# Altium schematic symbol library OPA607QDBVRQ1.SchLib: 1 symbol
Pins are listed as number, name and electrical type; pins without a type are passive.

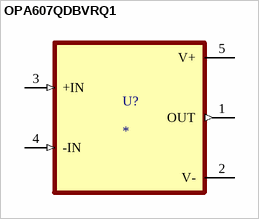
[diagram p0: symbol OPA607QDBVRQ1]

## OPA607QDBVRQ1
designator U?
MP: OPA336U
footprint OPA607QDBVRQ1
pins: 1 OUT (out), 2 V- (power), 3 +IN (in), 4 -IN (in), 5 V+ (power)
